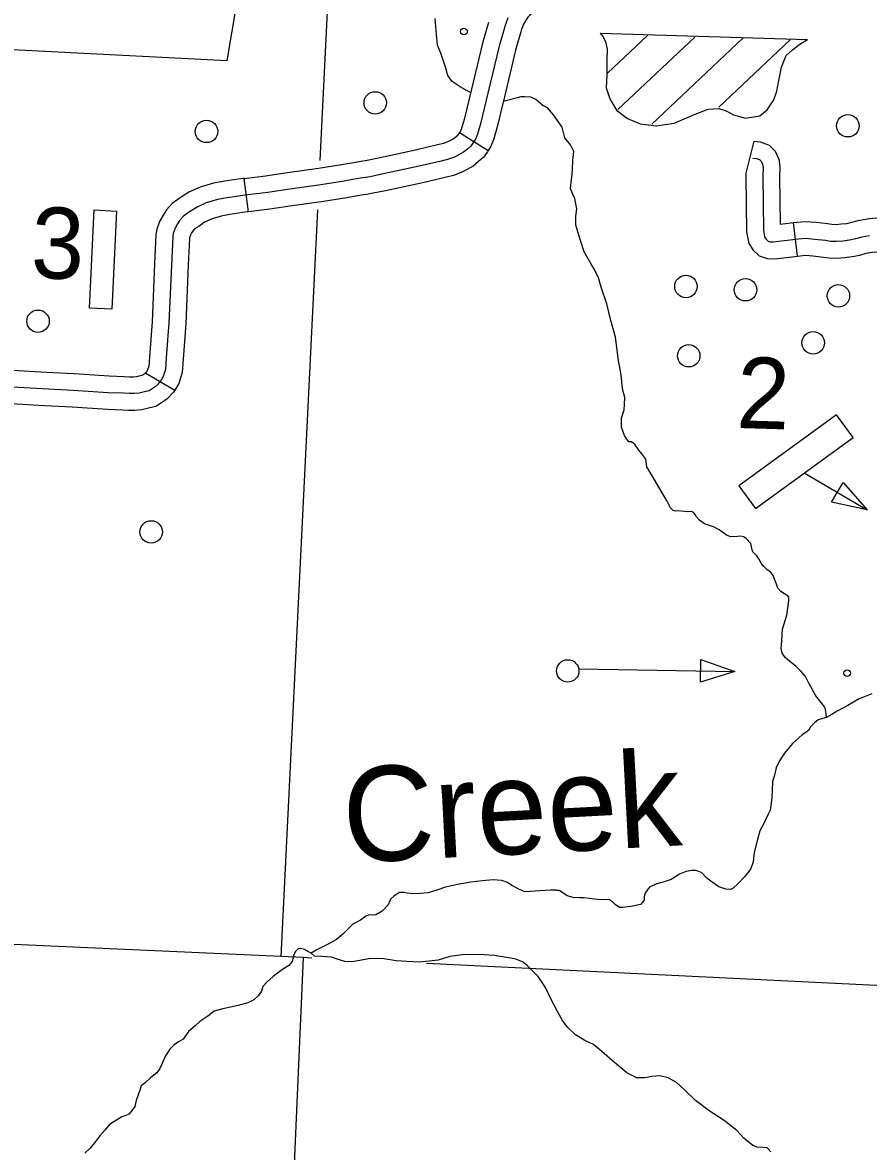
# Model space of a CAD drawing. Extents: x 653372 to 905732, y 627442 to 787275.
# Drawn here: x 673522 to 677287, y 774006 to 779033 of the extents above; entities that cross this region are included whole.
import ezdxf

# ---------------------------------------------------------------- set-up
doc = ezdxf.new("R2010")
doc.units = 0
for name, color, linetype in [('31', 7, 'Continuous'), ('32', 7, 'Continuous'), ('35', 7, 'Continuous'), ('4', 7, 'Continuous'), ('5', 7, 'Continuous'), ('56', 7, 'Continuous'), ('57', 7, 'Continuous'), ('6', 7, 'Continuous')]:
    doc.layers.add(name, color=color, linetype=linetype)

msp = doc.modelspace()

# ---------------------------------------------------------------- linework, layer by layer
at = {"layer": '31'}
for p, q in [((675467.5, 778543.1), (675595, 778464.1)), ((674527.3, 778190.2), (674508.6, 778339)), ((674070.3, 777472.4), (674199.6, 777396.4))]:
    msp.add_line(p, q, dxfattribs=at)
for points in [[(676112.4, 779261.3), (676086, 779245.6), (676007.6, 779200), (675868.9, 779123.5), (675804.9, 779084.9), (675781.9, 779067.4), (675771.1, 779057.3), (675760, 779040.4), (675750, 779023.4), (675741.2, 778997.8), (675739.7, 778992.2)], [(675681.6, 779054.8), (675669.7, 779020.3), (675643.6, 778928.7)], [(675595.4, 779033.2), (675571.1, 778947.7), (675520.7, 778737), (675488, 778601.4), (675476.5, 778561.5), (675471.3, 778549.3), (675467.5, 778543.1)], [(675739.7, 778992.2), (675716.2, 778909.7), (675666.6, 778702), (675633, 778563.1), (675618.1, 778511.1), (675604.8, 778479.9), (675595, 778464.1)], [(675643.6, 778928.7), (675593.7, 778719.5), (675560.5, 778582.3), (675547.3, 778536.3), (675538, 778514.6), (675529, 778499.9), (675516.7, 778483), (675502.2, 778470.1), (675485.2, 778455.4), (675463.7, 778443.5), (675444.5, 778433.8), (675418.3, 778424.4), (675385.9, 778416.7), (675287, 778393), (675121.5, 778357.9), (675069.3, 778346.9), (675016.5, 778338.3), (674953.3, 778326.8), (674850, 778311.1), (674711.6, 778290.9), (674613, 778276.6), (674512.1, 778263.9), (674433.3, 778252.1), (674389.1, 778244.8), (674339.2, 778229.8), (674298.6, 778211.4), (674265.7, 778189.6), (674237.7, 778170.8), (674222.2, 778153.2), (674211.5, 778137), (674200.7, 778116.9), (674193, 778094.4), (674190.2, 778079.5), (674173.2, 777696.6), (674161.5, 777539.4), (674157.6, 777488.5), (674148, 777456.6), (674133.9, 777432.7), (674116.9, 777414.3), (674099.2, 777402.3), (674084.8, 777393.3), (674065, 777388.4), (674041.3, 777382.8), (674018.5, 777381.1), (673996.1, 777381), (673971, 777382.6), (673903.6, 777384.6), (673746.8, 777394.8), (673473.6, 777410.1)], [(675028.1, 778416.2), (675055.5, 778420.7), (675106, 778431.3), (675270.5, 778466.2), (675368.5, 778489.7), (675396.9, 778496.4), (675414.9, 778502.9), (675428.6, 778509.8), (675442, 778517.2), (675452.6, 778526.4), (675460.8, 778533.7), (675466.7, 778541.8), (675467.5, 778543.1)], [(675595, 778464.1), (675591.3, 778458.1), (675572.6, 778432.4), (675551.7, 778413.8), (675528.4, 778393.6), (675498.7, 778377.1), (675474.2, 778364.8), (675439.7, 778352.4), (675403.3, 778343.8), (675303.6, 778319.8), (675137, 778284.5), (675083.1, 778273.2), (675052.3, 778268.1)], [(674508.6, 778339), (674603, 778350.9), (674700.8, 778365.1), (674838.9, 778385.3), (674940.9, 778400.8), (675003.7, 778412.2), (675028.1, 778416.2)], [(674508.6, 778339), (674501.9, 778338.2), (674421.6, 778326.2), (674372.1, 778318), (674312.8, 778300.2), (674262.1, 778277.2), (674224.1, 778252), (674187.8, 778227.7), (674162.5, 778198.8), (674147.1, 778175.6), (674131.8, 778147.1), (674120.3, 778113.6), (674115.5, 778088.2), (674109.8, 777959.9)], [(675052.3, 778268.1), (675029.2, 778264.4), (674965.6, 778252.9), (674861, 778236.9), (674722.4, 778216.7), (674623.1, 778202.2), (674527.3, 778190.2)], [(674527.3, 778190.2), (674522.4, 778189.6), (674444.9, 778178), (674406.1, 778171.6), (674365.6, 778159.4), (674335, 778145.6), (674307.3, 778127.2), (674287.6, 778114), (674282, 778107.6), (674276, 778098.5), (674269.7, 778086.8), (674265.7, 778075.1), (674264.9, 778070.9), (674259.7, 777953.2)], [(674109.8, 777959.9), (674098.4, 777701), (674086.7, 777545.1), (674083.4, 777502.3), (674078.7, 777486.8), (674070.3, 777472.4)], [(674259.7, 777953.2), (674248.1, 777692.1), (674236.2, 777533.8), (674231.7, 777474.7), (674217.2, 777426.3), (674199.6, 777396.4)], [(673101.1, 777506.1), (673477.8, 777484.9), (673628.3, 777476.5)], [(673628.3, 777476.5), (673751.4, 777469.7), (673907.1, 777459.5), (673974.5, 777457.5), (673998.2, 777456), (674015.6, 777456.1), (674029.9, 777457.2), (674047.4, 777461.3), (674055.2, 777463.2), (674058.2, 777465.1), (674067.6, 777471.5), (674073.4, 777477.7)], [(674199.6, 777396.4), (674194.4, 777387.6), (674166.1, 777357.1), (674140.2, 777339.5), (674114.4, 777323.4), (674082.6, 777315.5), (674052.7, 777308.4), (674021.4, 777306.1), (673994, 777306), (673967.6, 777307.6), (673900, 777309.7), (673742.3, 777319.9), (673619.9, 777326.8)], [(673619.9, 777326.8), (673469.4, 777335.2), (673092.7, 777356.4)]]:
    msp.add_lwpolyline(points, dxfattribs=at)
at = {"layer": '32'}
for p, q in [((676742, 778356.7), (676778.7, 778504.6)), ((676971.2, 777993.3), (676953.4, 778142.3))]:
    msp.add_line(p, q, dxfattribs=at)
for points in [[(676778.7, 778504.6), (676805.6, 778502.2), (676844.8, 778486.9), (676872.1, 778459.9), (676889.1, 778424.4), (676893.6, 778391.6), (676891.7, 778346.3), (676894.7, 778135.3), (676953.4, 778142.3)], [(676772.1, 778429.8), (676788.4, 778428.4), (676803.1, 778422.7), (676810.1, 778415.7), (676816.4, 778402.6), (676818.4, 778388.1), (676816.7, 778347.3), (676820.1, 778108.2), (676825.4, 778078.8), (676832.3, 778068.5), (676841.2, 778060), (676850.2, 778056.9), (676864.6, 778056.4), (676889.2, 778059.1), (676976, 778069.4), (677007.3, 778072.3), (677046.7, 778069.2), (677096, 778063.4), (677119, 778060.3), (677145.9, 778059.5), (677173.3, 778061.6), (677203.2, 778065), (677231.2, 778070.9), (677259.3, 778078.7), (677292.7, 778085.4)], [(676742, 778357.2), (676741.7, 778348.3), (676745.2, 778101), (676754.4, 778050), (676774.6, 778019.8), (676801.2, 777994.6), (676836.4, 777982.3), (676867.5, 777981.3), (676897.6, 777984.5), (676971.2, 777993.3)], [(676953.4, 778142.3), (676968.1, 778144), (677006.8, 778147.6), (677054.1, 778143.9), (677105.4, 778137.8), (677125.1, 778135.2), (677144.2, 778134.6), (677166.2, 778136.3), (677191.2, 778139.1), (677213.5, 778143.8), (677241.9, 778151.7), (677282.1, 778159.8), (677319.2, 778162.9), (677368.5, 778162.5), (677395.8, 778160.4)], [(676971.2, 777993.3), (676983.9, 777994.9), (677007.8, 777997.1), (677039.4, 777994.6), (677086.6, 777989), (677112.9, 777985.5), (677147.6, 777984.5), (677180.4, 777986.9), (677215.2, 777990.9), (677249, 777998), (677276.8, 778005.7), (677303.2, 778011), (677324.9, 778012.9), (677386.8, 778012.4)]]:
    msp.add_lwpolyline(points, dxfattribs=at)
at = {"layer": '35'}
for points in [[(675516.7, 778720.4), (675470, 778746.9), (675433.7, 778770.8), (675414.6, 778797.9), (675404.3, 778834.3), (675383.5, 778897.5), (675368.4, 778933.1), (675365.1, 778980.6), (675358.7, 779051)], [(675838.5, 778663.4), (675807.4, 778690.8), (675784.6, 778701.4), (675757.1, 778702.2), (675739.5, 778702.7), (675707.3, 778693.8), (675661.5, 778681)], [(676500.4, 776855.2), (676481.6, 776854.7), (676441, 776858.1), (676427.8, 776857.4), (676417.9, 776859.9), (676406.2, 776872.3), (676391.6, 776901.4), (676369.6, 776938.4), (676332.9, 777000.1), (676301.6, 777055), (676296, 777088.2), (676277.9, 777111.9), (676265.2, 777128.8), (676248.3, 777152.4), (676232.2, 777166.1), (676221.2, 777166.5), (676211.7, 777177.8), (676201.1, 777193.5), (676188.5, 777230.8), (676187.5, 777271.6), (676199.6, 777308.6), (676201.4, 777331.7), (676202.4, 777363.6), (676192.5, 777402.5), (676186.7, 777464.3), (676174.3, 777527.5), (676162, 777631.4), (676140, 777706.9), (676122.4, 777780.1), (676098.2, 777854.7), (676086.2, 777895.8), (676067.6, 777933.8), (676051.8, 777959.6), (676022.5, 778011.6), (676005.4, 778062.8), (675985.4, 778130.5), (675984.4, 778171.3), (675988.7, 778204.2), (675980.2, 778249.6), (675969.8, 778272), (675961.7, 778294.3), (675963.6, 778320.6), (675968, 778359), (675969.8, 778382.1), (675972, 778418.4), (675975.4, 778459), (675960.9, 778489.2), (675936.5, 778519.7), (675923.6, 778567.3), (675885.6, 778622.4), (675859.1, 778654), (675838.5, 778663.4)], [(677101.4, 775938.1), (677097.7, 775966.5), (677093.9, 775984.3), (677076.8, 776004.6), (677053.5, 776035), (677023.2, 776088.8), (677006.6, 776121.2), (676986.4, 776145), (676963.9, 776166.6), (676937, 776187.2), (676916.6, 776205.4), (676902.9, 776224.6), (676899.1, 776245.6), (676901.2, 776279.7), (676905, 776331.4), (676923.4, 776393.6), (676933, 776458.3), (676933.5, 776474.8), (676929.3, 776479.3), (676918.5, 776486.2), (676896.8, 776500.1), (676884, 776513.7), (676878, 776532.6), (676869.9, 776554.9), (676861.6, 776573.9), (676851, 776585.2), (676834.8, 776597.8), (676822, 776610.3), (676809.2, 776626.1), (676798.8, 776645.1), (676790.4, 776657.5), (676773.3, 776675.6), (676769.2, 776684.6), (676767.4, 776700), (676763.4, 776713.4), (676743.1, 776734.9), (676731.3, 776743), (676718.1, 776745.6), (676703.8, 776744.9), (676675.1, 776742.5), (676655.5, 776750.8), (676643.7, 776759.9), (676622.3, 776774.4), (676597.4, 776787.3), (676558.2, 776800.6), (676535.5, 776816.7), (676521.7, 776832.5), (676515.4, 776842.6), (676509, 776850.5), (676500.4, 776855.2)], [(677301.9, 776043.8), (677243, 776019.2), (677195.1, 775992.3), (677148, 775966.3), (677124.7, 775950.9), (677101.4, 775938.1), (677063.3, 775927.1), (677046.7, 775914.1), (677030.1, 775897.1), (677020.1, 775879.9), (676992.6, 775860.5), (676949.7, 775822.7), (676913.3, 775779.3), (676892.1, 775744.9), (676876.3, 775714.3), (676870.1, 775687.6), (676861, 775651.4), (676858.5, 775615.1), (676857.5, 775580.1), (676852.4, 775546.5), (676850.4, 775525), (676840.5, 775507.8), (676821.7, 775466.6), (676804.6, 775433.4), (676794, 775394.6), (676781.8, 775349.1), (676777.1, 775326.4), (676774.8, 775294.1), (676763.1, 775263.4), (676736.5, 775230.5), (676704.5, 775196.4), (676685, 775178.1), (676672.7, 775171.8), (676652.6, 775173.7), (676621.9, 775184.1), (676591.5, 775205.2), (676567.8, 775222.1), (676544.3, 775247.1), (676519, 775257.3), (676501.4, 775256.5), (676475.7, 775251.8), (676447, 775240.6), (676409.9, 775216.1), (676377.3, 775206.3), (676344.8, 775196.8), (676314.8, 775184.2), (676305, 775173.7), (676293.7, 775156.5), (676289.2, 775140.5), (676288.7, 775124.3), (676272, 775105.9), (676229.9, 775096.4), (676192.1, 775092.2), (676179.9, 775092.5), (676160.1, 775105.3), (676148.4, 775117.8), (676135.1, 775126.2), (676115, 775128.2), (676098.7, 775126), (676066.5, 775129.6), (676022.2, 775135), (676000.6, 775134.3), (675972.4, 775136.5)], [(675972.4, 775136.5), (675945.7, 775144.1), (675923.2, 775159.6), (675910, 775168), (675900.5, 775167), (675897.9, 775169.8), (675872.3, 775169.2), (675824.6, 775166.6), (675782.8, 775163.8), (675757.1, 775161.9), (675730.5, 775173.4), (675700, 775189.2), (675680.2, 775203.3), (675654.9, 775212.1), (675617.2, 775215.9), (675567.2, 775210.7), (675517.2, 775205.5), (675457.6, 775195.1), (675404.6, 775181.9), (675366.5, 775169.5), (675327.1, 775157.2), (675293.3, 775154.2), (675259.6, 775152.5), (675234.1, 775156), (675220.7, 775159.1), (675200.4, 775158.3), (675175.8, 775144.3), (675159.1, 775128.6), (675148.9, 775103.3), (675122.5, 775075.8), (675095, 775059.1), (675078.8, 775058.2), (675066.7, 775058.6), (675050.4, 775053.7), (675025.6, 775035.5), (674992.7, 775017.6), (674946.9, 774973.2), (674919.3, 774949.8), (674876.8, 774925.4), (674829.6, 774902.1), (674806.3, 774889.3), (674791.7, 774896.5), (674777.1, 774905), (674759.7, 774909.6), (674748.9, 774907.2), (674735, 774894.1), (674727.7, 774876.8), (674721.6, 774851.4), (674707.6, 774834.3), (674678.7, 774816.3)], [(676853.5, 774003), (676836.2, 774021.4), (676817.2, 774023.1), (676792.5, 774024), (676772.6, 774031.3), (676732.4, 774064.8), (676701, 774099.3), (676645.3, 774143.5), (676578.3, 774185.8), (676518.2, 774232.3), (676467.1, 774282), (676432.5, 774312.7), (676395.1, 774332.8), (676358.5, 774342.9), (676322.6, 774339.5), (676289.9, 774332.6), (676256.4, 774333.6), (676212.3, 774355.1), (676148, 774409.6), (676110.9, 774442.1), (676062.9, 774481.5), (676025.4, 774499.4), (675983.7, 774524.2), (675946.8, 774561.1), (675925.2, 774588.6), (675902.9, 774628.4), (675872.3, 774687.5), (675849.2, 774736.3), (675816.5, 774785.2), (675768.8, 774833.6), (675746.9, 774849.9), (675718.2, 774862), (675684.8, 774867.5), (675621.4, 774878.3), (675554.4, 774882.6), (675478.3, 774881.5), (675424.4, 774874.2), (675371.6, 774856.7), (675289.7, 774848), (675232.7, 774850.8), (675184.7, 774854.5), (675130.2, 774862.8), (675101.2, 774864.8), (675062, 774862.6), (675022.6, 774856), (674987.8, 774850.3), (674956.5, 774851.3), (674922.2, 774861.2), (674897.8, 774870.9), (674855.5, 774873.3), (674820.9, 774875.5), (674806.3, 774889.3)], [(674678.7, 774816.3), (674637.4, 774785.2), (674609.6, 774759), (674591.6, 774740.7), (674585.5, 774719.3), (674570.1, 774698.2), (674552.1, 774681.2), (674524.7, 774667.2), (674481.2, 774655.1), (674413.4, 774640.9), (674375.3, 774629.9), (674346.4, 774607.9), (674310.6, 774584.7), (674289.8, 774565.1), (674260.7, 774539), (674236.8, 774506), (674216.2, 774493.2), (674195.6, 774478.9), (674177.5, 774460.6), (674157.8, 774431.6), (674143.3, 774396.9), (674133.2, 774374.3), (674119.1, 774355.9), (674092.9, 774335.1), (674067.9, 774311.6), (674050.3, 774297.8), (674044.3, 774277.7), (674028.1, 774232.4), (674021.9, 774205.6), (674005.1, 774183.2), (673995.3, 774171.3), (673981.6, 774165), (673963.9, 774160.2), (673940.6, 774144.7), (673909, 774125.4), (673888, 774100.4), (673864.3, 774074.2), (673841.9, 774043.8), (673820.9, 774018.9), (673798.7, 773998)]]:
    msp.add_lwpolyline(points, dxfattribs=at)
at = {"layer": '4'}
for points in [[(674808.9, 774866.9), (674771.1, 774868.7), (674671.6, 774873.5), (671137.5, 775032.9)], [(678567.5, 774684.4), (675320.6, 774842)]]:
    msp.add_lwpolyline(points, dxfattribs=at)
at = {"layer": '5'}
for points in [[(674930.7, 780168.6), (674845, 778418.5)], [(674834.3, 778199.2), (674671.6, 774873.5)], [(674771.1, 774868.7), (674638.3, 771837)]]:
    msp.add_lwpolyline(points, dxfattribs=at)
at = {"layer": '56'}
for p, q in [((676539.2, 776095), (676540.8, 776196.9)), ((676540.8, 776196.9), (676693, 776143.5)), ((676693, 776143.5), (676539.2, 776095))]:
    msp.add_line(p, q, dxfattribs=at)
msp.add_lwpolyline([(673840.2, 778198.8), (673940.1, 778194), (673919.3, 777757), (673819.4, 777761.8)], close=True, dxfattribs=at)
msp.add_lwpolyline([(675999, 776154.7), (676693, 776143.5)], dxfattribs=at)
for centre, radius in [((675486.5, 778993.4), 15), ((675092, 778675.4), 50), ((674340.4, 778548.5), 50), ((677195.9, 778573.7), 50), ((676475.1, 777857.9), 50), ((676740, 777843.2), 50), ((677153.6, 777816.1), 50), ((673590.6, 777702.9), 50), ((677041.6, 777607), 50), ((676487.3, 777549.4), 50), ((674094.6, 776764.6), 50), ((675948.7, 776145.4), 50), ((677192.9, 776135.9), 15)]:
    msp.add_circle(centre, radius, dxfattribs=at)
at = {"layer": '57'}
for p, q in [((676092.6, 778986), (677016.2, 778958.3)), ((676125.3, 778807.5), (676304.4, 778976.1)), ((676172, 778645.4), (676515.2, 778968.6)), ((676322.4, 778581), (676728.9, 778963.8)), ((676620.7, 778655.9), (676939.1, 778955.7)), ((677145.4, 777286.8), (676711, 776970.2)), ((677219, 777185.8), (677145.4, 777286.8)), ((676784.7, 776869.2), (677219, 777185.8)), ((677123.4, 776896.9), (677175.1, 776984.9)), ((677175.1, 776984.9), (677281.2, 776863.4)), ((676711, 776970.2), (676784.7, 776869.2)), ((677281.2, 776863.4), (677123.4, 776896.9))]:
    msp.add_line(p, q, dxfattribs=at)
for points in [[(676092.6, 778986), (676105.3, 778971.1), (676117, 778948.7), (676124.3, 778915.3), (676122.8, 778865.6), (676122.2, 778800.7), (676120.5, 778742.8), (676135.6, 778694), (676165.9, 778643.4), (676214.4, 778606), (676271.7, 778582.2), (676341.9, 778573.2), (676422.4, 778585.9), (676516.1, 778624.6), (676573.4, 778647.7), (676621.8, 778650.4), (676654.7, 778639.7), (676687.3, 778622.2), (676740.7, 778608.1), (676803.2, 778617.3), (676837.1, 778643.9), (676866.1, 778688.6), (676879.7, 778728.3), (676888, 778775), (676900.8, 778834), (676921.7, 778887.2), (676948.7, 778911.3), (676982.6, 778936.5), (677016.2, 778958.3)], [(677001.8, 777027.5), (677281.2, 776863.4)]]:
    msp.add_lwpolyline(points, dxfattribs=at)
at = {"layer": '6'}
for points in [[(672247.2, 779726.4), (672376.8, 779728.7), (672525, 779840.9), (672648.1, 779840.9), (672735.1, 780264.2), (673997.2, 780209.2), (673993.7, 780137), (674589.2, 779798), (674431.5, 778863.2)], [(674431.5, 778863.2), (673535.4, 778908.9), (672424.5, 778961.8), (672451.7, 779560.4), (672240.8, 779571.1)]]:
    msp.add_lwpolyline(points, dxfattribs=at)

# ---------------------------------------------------------------- texts
at = {"layer": '35'}
msp.add_text('Creek', height=422.4, rotation=3.016, dxfattribs=at).set_placement((674957.3, 775289.8))
at = {"layer": '56'}
msp.add_text('3', height=316.8, rotation=358.28, dxfattribs=at).set_placement((673556.5, 777896.2))
at = {"layer": '57'}
msp.add_text('2', height=316.8, rotation=358.28, dxfattribs=at).set_placement((676697.3, 777227.9))

doc.saveas('drawing.dxf')
